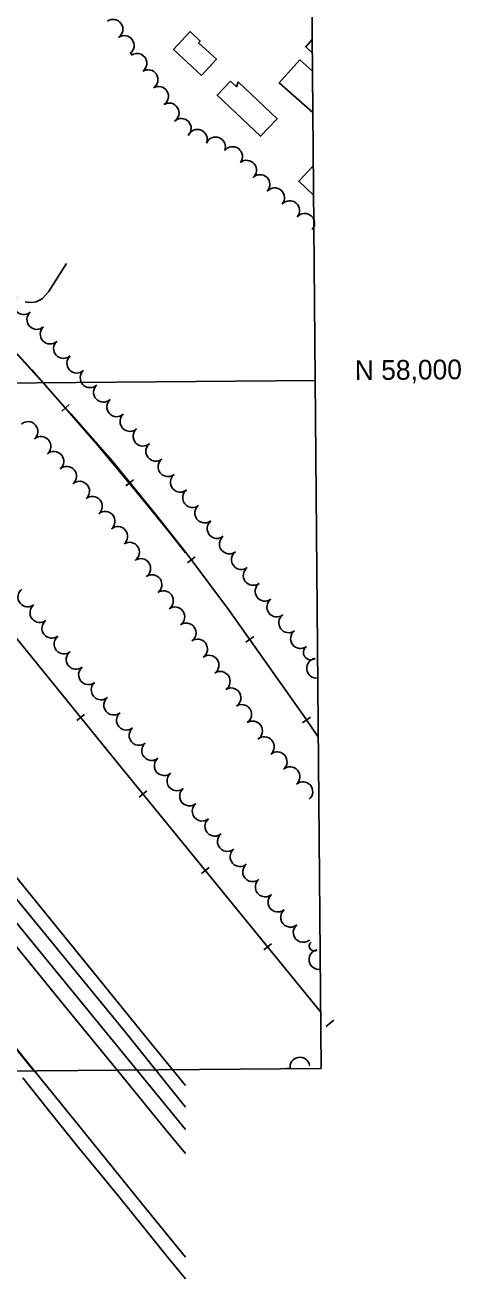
# Model space of a CAD drawing. Extents: x -2233 to 187241, y 4582 to 150524.
# Drawn here: x 119714 to 120156, y 57220 to 58491 of the extents above; entities that cross this region are included whole.
import ezdxf

# ---------------------------------------------------------------- set-up
doc = ezdxf.new("R2010")
doc.units = 0
for name, color, linetype in [('60', 7, 'Continuous'), ('BLDG', 7, 'Continuous'), ('GRID', 7, 'Continuous'), ('RD_X_RR_1', 7, 'Continuous'), ('ROAD', 7, 'Continuous'), ('RR', 7, 'Continuous'), ('TREES', 7, 'Continuous'), ('WATER', 7, 'Continuous')]:
    doc.layers.add(name, color=color, linetype=linetype)

msp = doc.modelspace()

# ---------------------------------------------------------------- linework, layer by layer
at = {"layer": '60'}
for p, q in [((119990.7, 60130.9), (120014.2, 57433.2)), ((120014.2, 57433.2), (115014.4, 57389.6))]:
    msp.add_line(p, q, dxfattribs=at)
at = {"layer": 'BLDG'}
msp.add_line((119992.4, 58456.2), (120005.4, 58444.6), dxfattribs=at)
for points in [[(119881.3, 58484.8), (119891.6, 58475.2), (119889.9, 58473.3), (119907.9, 58456.7), (119892.8, 58440.4), (119864.5, 58466.7)], [(119922.2, 58434.6), (119928.2, 58428.9), (119930, 58433.8), (119969.4, 58396.3), (119952.7, 58378.7), (119908.7, 58420.5)]]:
    msp.add_lwpolyline(points, close=True, dxfattribs=at)
for points in [[(120005.3, 58463.1), (119998.4, 58469.3), (120005.1, 58476.7)], [(120005.8, 58403.1), (120005.5, 58402.7), (119971.6, 58432.8), (119992.4, 58456.2)]]:
    msp.add_lwpolyline(points, dxfattribs=at)
at = {"layer": 'GRID'}
for p, q in [((119990.7, 60130.9), (120014.2, 57433.2)), ((120008.2, 58130.9), (115008.3, 58087.3))]:
    msp.add_line(p, q, dxfattribs=at)
at = {"layer": 'RD_X_RR_1'}
for points in [[(118139.8, 59521.5), (118178.2, 59482.2), (118208.9, 59451.8), (118237.8, 59421.2), (118337.6, 59298.2), (118459.2, 59150.2), (118573.6, 59010.6), (118683.6, 58875.6), (118800.5, 58732.8), (118900.7, 58610.6), (118988.3, 58503.9), (119083, 58387.8), (119174, 58276.9), (119248.8, 58185.2), (119322.3, 58095.8), (119374.5, 58031.6), (119545.6, 57822.5), (119603.6, 57750.6), (119648, 57695.7), (119707.1, 57624.7), (119782.9, 57531.4), (119841.9, 57458.4), (119876.5, 57416)], [(119876.5, 57956), (119860.3, 57976.8), (119841.9, 57999.7), (119823.2, 58022.3), (119788.2, 58064.7), (119754.8, 58103.3), (119720.6, 58142.2), (119673, 58194.1), (119623.3, 58248.9), (119569, 58308.4), (119463.2, 58423.2), (119388.8, 58503.7), (119366.4, 58528.3), (119346.3, 58549.4), (119322.8, 58575.6), (119243.6, 58661.3), (119177.8, 58733.1), (119127.9, 58788.1), (119069.4, 58850.8), (119012.5, 58912.6), (118958, 58971.5), (118914.6, 59019.9), (118864.1, 59074.2), (118810.4, 59132.8)], [(119876.5, 57393.8), (119815.4, 57470.4), (119699.6, 57611.9), (119599.1, 57732.6), (119483.4, 57874.5), (119377.4, 58004.2), (119323, 58071.7), (119269.7, 58136.6), (119202.7, 58218.4), (119128, 58309.4), (119013, 58450.7), (118954, 58522.4), (118900.4, 58588.6), (118840.7, 58661.8)], [(118817.4, 58546.2), (118872.5, 58479), (118935, 58401.6), (118985.3, 58339.7), (119026.8, 58288.4), (119085.9, 58217.2), (119135.1, 58155.7), (119185.6, 58093.4), (119235.9, 58031.5), (119294, 57959.5), (119324.3, 57922.7), (119381.4, 57852.1), (119444.1, 57775.2), (119503.3, 57701.9), (119613.5, 57566.6), (119669.9, 57497.2), (119717.1, 57438.6), (119769.6, 57373.9), (119831.9, 57296.5), (119876.5, 57241.8)], [(119876.5, 57371.3), (119800.7, 57464.2), (119703.9, 57582.8), (119682.6, 57608.6), (119642.5, 57658.2), (119589.1, 57723.7), (119541.1, 57781.4), (119500.8, 57830.8), (119464.3, 57876.1), (119430.3, 57917), (119382.2, 57976.3), (119348.9, 58015.3), (119317, 58055.1), (119275.8, 58105.7), (119186.8, 58214.4), (119150.1, 58259.3), (119121.8, 58293.3), (119084.2, 58339.8), (119050.2, 58381.3), (119004.9, 58435.5), (118966, 58483.6), (118923.3, 58536.1)], [(118929.1, 58505.2), (118960.4, 58466.4), (119005.8, 58411.7), (119041.9, 58367.8), (119082.5, 58317.7), (119118.5, 58273.4), (119165.2, 58216.5), (119208.1, 58163.5), (119258, 58102.9), (119296.2, 58056), (119378.3, 57955.6), (119422.7, 57901.4), (119457.8, 57858.6), (119488.2, 57821.6), (119520.4, 57781.7), (119557.2, 57737.6), (119643.9, 57631.6), (119688.7, 57576.7), (119708.9, 57552.3), (119754.2, 57496.5), (119804.9, 57434.3), (119856.8, 57370.9), (119876.5, 57346.8)], [(119711.7, 57423.6), (119735.2, 57394.2), (119766.4, 57355.1), (119809, 57303.1), (119859.2, 57241), (119876.5, 57219.6)]]:
    msp.add_lwpolyline(points, dxfattribs=at)
at = {"layer": 'ROAD'}
msp.add_lwpolyline([(120006.3, 58349), (119991.3, 58333.1), (120006.5, 58318.6)], dxfattribs=at)
at = {"layer": 'RR'}
for p, q in [((119751.4, 58099.8), (119758.8, 58106.5)), ((119816.3, 58024), (119824, 58030.3)), ((119878.5, 57946), (119886.5, 57952)), ((119937.6, 57865.5), (119945.8, 57871.3)), ((119766.5, 57786), (119774.3, 57792.3)), ((119995, 57783.8), (120003.3, 57789.4)), ((119829.6, 57708.4), (119837.3, 57714.7)), ((119892.7, 57630.8), (119900.5, 57637.1)), ((119955.9, 57553.3), (119963.7, 57559.6)), ((120019.1, 57475.8), (120026.8, 57482.1))]:
    msp.add_line(p, q, dxfattribs=at)
for points in [[(118571.9, 59392.5), (118824.7, 59116.9), (119054.9, 58866.7), (119335.7, 58561.8), (119609.3, 58264.6), (119760.5, 58097.1), (119802.2, 58049.3), (119843.5, 57998.6), (119878.2, 57954.8), (119920.3, 57898.8), (119997.7, 57788.7), (120011.3, 57768.8)], [(118540.9, 59302.7), (118697, 59111.2), (118882.4, 58883.2), (119027, 58705.6), (119268.8, 58407.3), (119549.6, 58061.4), (119807.8, 57743), (120013.7, 57490.2)], [(119722.9, 57430.6), (119662.3, 57505.7), (119597.9, 57585.1), (119527, 57673.1), (119458.6, 57757), (119389.8, 57842.4), (119315.7, 57933.4), (119257.3, 58004.9), (119190.4, 58086.8), (119128.6, 58163.8), (119064.2, 58242.6), (119003.7, 58317.1), (118953.3, 58379.2), (118901.1, 58443.6), (118858.3, 58496.6), (118774.5, 58599.7), (118700.3, 58690.1), (118619.3, 58790.6), (118538.8, 58890.1), (118481.3, 58960.3)]]:
    msp.add_lwpolyline(points, dxfattribs=at)
at = {"layer": 'TREES'}
for centre, radius, start, end in [((119803.2, 58487.2), 10, 304.2303, 124.2303), ((119814.6, 58470.8), 10, 305.4251, 125.4251), ((119821.1, 58461.7), 1.12, 305.4618, 125.4618), ((119827.5, 58452.7), 10, 305.4618, 125.4618), ((119838.7, 58436.1), 10, 302.4951, 122.4951), ((119849.4, 58419.2), 10, 302.2901, 122.2901), ((119860.1, 58402.3), 10, 302.2901, 122.2901), ((119872.4, 58386.7), 10, 314.3131, 134.3131), ((119888.6, 58375.6), 10, 337.1877, 157.1877), ((119907.1, 58367.9), 10, 337.5936, 157.5936), ((119924.3, 58358.1), 10, 322.9457, 142.9457), ((119938.5, 58344.3), 10, 308.6737, 128.6737), ((119952.1, 58329.7), 10, 317.2044, 137.2044), ((119967, 58316.3), 10, 319.1903, 139.1903), ((119982.2, 58303.3), 10, 319.5677, 139.5677), ((119997.4, 58290.4), 10, 319.7323, 139.7323), ((119712.7, 58207.7), 10, 130.9259, 310.9259), ((119726, 58192.8), 10, 132.3893, 312.3893), ((119739.5, 58178), 10, 132.3893, 312.3893), ((119753, 58163.3), 10, 132.3893, 312.3893), ((119766.5, 58148.5), 10, 132.3893, 312.3893), ((119780, 58133.7), 10, 132.3893, 312.3893), ((119793.4, 58118.9), 10, 132.3893, 312.3893), ((119806.9, 58104.2), 10, 132.3893, 312.3893), ((119820.3, 58089.3), 10, 131.6229, 311.6229), ((119717.1, 58079.2), 10, 310.8558, 130.8558), ((119730.2, 58064.1), 10, 310.8558, 130.8558), ((119833.6, 58074.4), 10, 131.6227, 311.6227), ((119743.3, 58049), 10, 310.8558, 130.8558), ((119846.5, 58059), 10, 128.4004, 308.4004), ((119858.9, 58043.4), 10, 128.4004, 308.4004), ((119756.3, 58033.8), 10, 310.8558, 130.8558), ((119871.3, 58027.7), 10, 128.4004, 308.4004), ((119769.4, 58018.7), 10, 310.5829, 130.583), ((119883.7, 58012), 10, 128.4004, 308.4004), ((119782.3, 58003.4), 10, 309.9598, 129.9598), ((119795.2, 57988.1), 10, 309.9598, 129.9598), ((119896.1, 57996.4), 10, 128.4004, 308.4004), ((119808, 57972.8), 10, 309.9598, 129.9598), ((119908.6, 57980.7), 10, 128.4004, 308.4004), ((119921, 57965), 10, 128.4004, 308.4004), ((119820, 57956.8), 10, 303.8742, 123.8742), ((119933.2, 57949.2), 10, 126.8924, 306.8924), ((119831.3, 57940.3), 10, 304.6739, 124.6739), ((119842.7, 57923.9), 10, 305.2657, 125.2657), ((119945.2, 57933.2), 10, 126.7722, 306.7722), ((119716.9, 57911.3), 10, 127.5421, 307.5421), ((119854.3, 57907.6), 10, 305.2657, 125.2657), ((119957.2, 57917.1), 10, 126.7722, 306.7722), ((119969.1, 57901.1), 10, 126.7722, 306.7722), ((119729.1, 57895.4), 10, 127.5421, 307.5421), ((119865.8, 57891.2), 10, 305.2657, 125.2657), ((119981.1, 57885.1), 10, 126.7722, 306.7722), ((119741.2, 57879.6), 10, 127.5421, 307.5421), ((119877.4, 57874.9), 10, 305.2657, 125.2657), ((119753.5, 57863.7), 10, 127.9114, 307.9114), ((119888.9, 57858.6), 10, 305.2657, 125.2657), ((119993.1, 57869.1), 10, 126.7722, 306.7722), ((119765.8, 57848), 10, 127.9115, 307.9115), ((120003.6, 57855.1), 7.51, 126.7722, 306.7722), ((119900.5, 57842.2), 10, 305.2657, 125.2657), ((120009.4, 57839.1), 10, 97.8367, 277.8367), ((119778.3, 57832.4), 10, 129.7708, 309.7708), ((119911.8, 57825.8), 10, 303.9292, 123.9292), ((119791.1, 57817), 10, 129.7708, 309.7708), ((119922.8, 57809.1), 10, 302.7598, 122.7598), ((119803.9, 57801.6), 10, 129.7708, 309.7708), ((119816.7, 57786.3), 10, 129.7708, 309.7708), ((119933.6, 57792.3), 10, 302.7598, 122.7598), ((119829.5, 57770.9), 10, 129.7708, 309.7708), ((119944.5, 57775.5), 10, 303.2513, 123.2513), ((119956.5, 57759.5), 10, 310.4946, 130.4946), ((119842.3, 57755.5), 10, 129.7708, 309.7708), ((119969.5, 57744.3), 10, 310.4946, 130.4946), ((119855.1, 57740.2), 10, 129.7708, 309.7708), ((119867.9, 57724.8), 10, 129.7708, 309.7708), ((119982.5, 57729.1), 10, 310.4946, 130.4946), ((119880.7, 57709.4), 10, 129.7708, 309.7708), ((119995.5, 57713.9), 10, 310.4946, 130.4946), ((119893.5, 57694), 10, 129.7708, 309.7708), ((120002, 57706.3), 2.3294430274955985e-11, 309.1598, 129.1598), ((119906.3, 57678.7), 10, 129.7708, 309.7708), ((119919, 57663.3), 10, 129.7708, 309.7708), ((119931.8, 57647.9), 10, 129.7708, 309.7708), ((119944.6, 57632.6), 10, 129.7708, 309.7708), ((119957.4, 57617.2), 10, 129.7708, 309.7708), ((119970.2, 57601.8), 10, 129.7708, 309.7708), ((119983, 57586.4), 10, 129.7708, 309.7708), ((119995.8, 57571.1), 10, 129.7708, 309.7708), ((120007, 57557.4), 5.05, 128.4367, 308.4367), ((120011.7, 57543.6), 10, 99.4057, 279.4057), ((119992.5, 57434.5), 10, 9.2223, 188.8625), ((120002.4, 57436), 0.0134, 324.0309, 144.0309), ((119980.3, 57423.1), 10, 78.0943, 102.9057)]:
    msp.add_arc(centre, radius, start, end, dxfattribs=at)
at = {"layer": 'WATER'}
msp.add_lwpolyline([(119714.3, 58210.8), (119716.1, 58210.3), (119720.9, 58209.9), (119725.3, 58210.7), (119731.5, 58213.7), (119738, 58220.7), (119756.2, 58249.7)], dxfattribs=at)

# ---------------------------------------------------------------- texts
at = {"layer": 'GRID'}
msp.add_text('N 58,000', height=20, rotation=0.5, dxfattribs=at).set_placement((120048.2, 58131.3))

doc.saveas('drawing.dxf')
